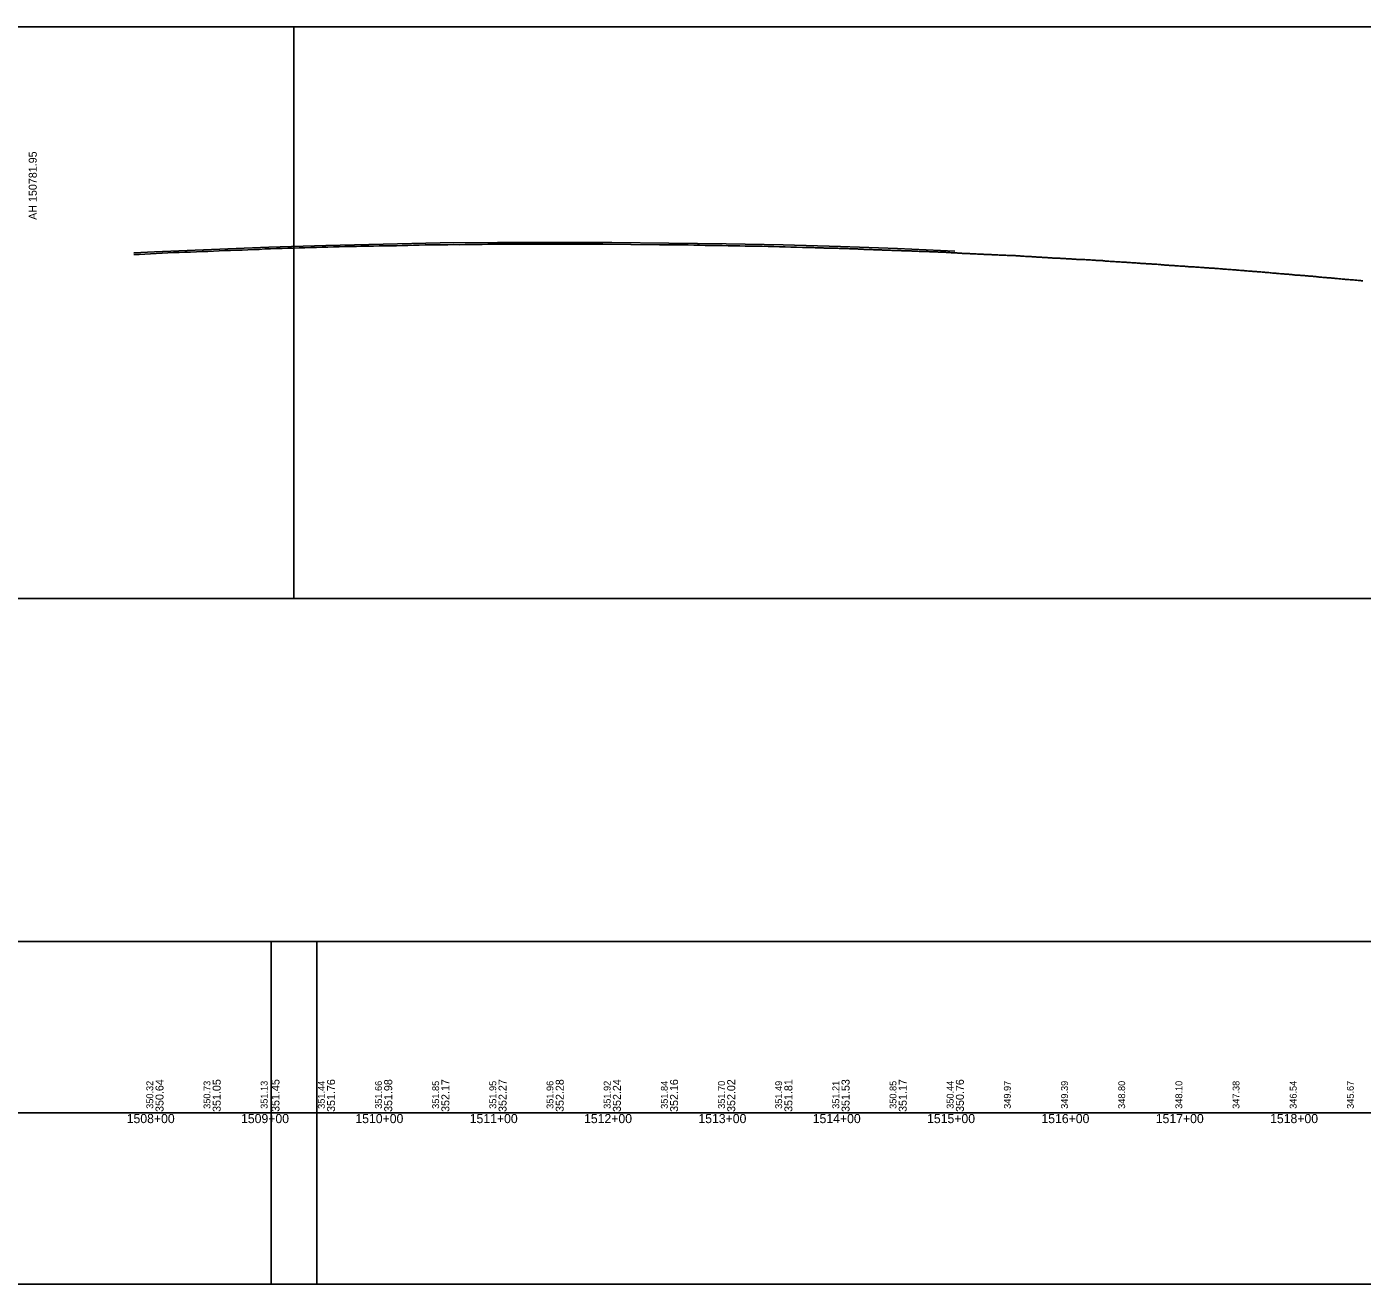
# Model space of a CAD drawing. Extents: x 2898 to 49495, y -15038 to -13538.
# Drawn here: x 40242 to 41410, y -15038 to -13938 of the extents above; entities that cross this region are included whole.
import ezdxf

# ---------------------------------------------------------------- set-up
doc = ezdxf.new("R2010")
doc.units = 0
for name, color, linetype in [('RD_DDB_Profile_EX', 7, 'Continuous'), ('RD_DDB_Profile_PR', 7, 'Continuous'), ('RD_DDB_StaTX', 7, 'Continuous'), ('RD_DDB_StripGrade', 7, 'Continuous'), ('RD_GPK_Profile_Cell', 7, 'Continuous'), ('RD_SHT_ShtClip', 7, 'Continuous')]:
    doc.layers.add(name, color=color, linetype=linetype)

msp = doc.modelspace()

# ---------------------------------------------------------------- linework, layer by layer
at = {"layer": 'RD_DDB_Profile_EX'}
for points in [[(40335.3, -14137.8), (40340.1, -14137.6), (40345.1, -14137.3), (40350.1, -14137.1), (40355.1, -14136.8), (40360.1, -14136.6), (40365.1, -14136.4), (40370.1, -14136.1), (40375.1, -14135.9), (40380.1, -14135.7), (40385.1, -14135.6), (40390.1, -14135.4), (40395.1, -14135.1), (40400.1, -14135), (40405.1, -14134.8), (40410.1, -14134.5), (40415.1, -14134.3), (40420.1, -14134.1), (40425.1, -14133.9), (40430.1, -14133.8), (40435.1, -14133.6), (40440.1, -14133.4), (40445.1, -14133.2), (40450.1, -14132.9), (40455.1, -14132.8), (40460.1, -14132.6), (40465.1, -14132.5), (40470.1, -14132.2), (40475.1, -14132.1), (40480.1, -14132), (40485.1, -14131.9), (40490.1, -14131.6), (40495.1, -14131.5), (40500.1, -14131.4), (40505.1, -14131.2), (40510.1, -14131), (40515.1, -14130.9), (40520.1, -14130.8), (40525.1, -14130.7), (40530.1, -14130.6), (40534, -14130.5), (40535.1, -14130.5), (40540.1, -14130.3), (40545.1, -14130.3), (40550.1, -14130.2), (40555.1, -14130.1), (40560.1, -14130.1), (40565.1, -14130), (40570.1, -14129.9), (40575.1, -14129.7), (40580.1, -14129.6), (40585.1, -14129.6), (40590.1, -14129.4), (40595.1, -14129.3), (40600.1, -14129.3), (40605.1, -14129.2), (40610.1, -14129.2), (40615.1, -14129.1), (40620.1, -14129.2), (40625.1, -14129.1), (40630.1, -14129), (40635.1, -14129), (40640.1, -14128.9), (40645.1, -14128.8), (40650.1, -14128.8), (40655.1, -14128.7), (40660.1, -14128.7), (40665.1, -14128.7), (40670.1, -14128.7), (40675.1, -14128.7), (40699.7, -14128.7), (40700.3, -14128.7), (40725.1, -14128.7), (40730.1, -14128.6), (40735.1, -14128.7), (40740.1, -14128.8), (40745, -14128.8), (40745.7, -14128.8), (40770, -14129), (40770.5, -14129), (40795.1, -14129.2), (40800.1, -14129.2), (40805.1, -14129.3), (40810.1, -14129.4), (40815.1, -14129.4), (40820.1, -14129.4), (40825.1, -14129.6), (40830.1, -14129.6), (40835.1, -14129.7), (40840.1, -14129.7), (40845.1, -14129.8), (40850.1, -14129.9), (40855.1, -14130), (40860.1, -14130.1), (40865.4, -14130.1), (40870.1, -14130.3), (40871.6, -14130.3), (40875.1, -14130.3), (40880.1, -14130.4), (40885.1, -14130.5), (40890.1, -14130.6)], [(40890.1, -14130.6), (40895.1, -14130.8), (40900.1, -14130.9), (40905.1, -14131.1), (40910.1, -14131.2), (40915.1, -14131.4), (40920.1, -14131.5), (40925.1, -14131.6), (40930.2, -14131.7), (40931.2, -14131.8), (40932.2, -14131.8), (40933.2, -14131.9), (40934.2, -14131.9), (40935.2, -14131.9), (40936.2, -14132), (40937.2, -14132), (40938.2, -14132), (40939.2, -14132.1), (40940.2, -14132.1), (40941.2, -14132.1), (40942.2, -14132.1), (40943.2, -14132.1), (40944.2, -14132.2), (40945.2, -14132.2), (40946.2, -14132.2), (40947.2, -14132.2), (40948.2, -14132.3), (40949.2, -14132.3), (40950.2, -14132.3), (40951.2, -14132.3), (40952.2, -14132.4), (40953.2, -14132.4), (40954.2, -14132.5), (40955.2, -14132.5), (40956.2, -14132.5), (40957.2, -14132.6), (40958.2, -14132.5), (40959.2, -14132.5), (40960.2, -14132.6), (40961.2, -14132.7), (40962.2, -14132.7), (40963.2, -14132.7), (40964.2, -14132.8), (40965.2, -14132.7), (40966.2, -14132.7), (40967.2, -14132.8), (40968.2, -14132.9), (40969.2, -14133), (40970.2, -14133), (40971.2, -14133.1), (40972.2, -14133.1), (40973.2, -14133.1), (40974.2, -14133.2), (40974.8, -14133.2), (40975.2, -14133.3), (40976.2, -14133.3), (40977.2, -14133.3), (40978.2, -14133.3), (40979.2, -14133.4), (40980.2, -14133.4), (40981.2, -14133.4), (40982.2, -14133.5), (40983.2, -14133.5), (40984.2, -14133.6), (40985.2, -14133.6), (40986.2, -14133.6), (40987.2, -14133.7), (40988.2, -14133.7), (40989.2, -14133.7), (40990.2, -14133.8), (40991.2, -14133.8), (40992.2, -14133.8), (40993.2, -14133.8), (40994.2, -14133.9), (40995.2, -14133.9), (40995.5, -14133.9), (40996.2, -14133.9), (40996.7, -14134), (40997.2, -14134), (40998.3, -14134.1), (40999.2, -14134.1), (41000.2, -14134.1), (41001.2, -14134.1), (41002.2, -14134.2), (41003.2, -14134.2), (41004.2, -14134.3), (41005.2, -14134.3), (41006.2, -14134.3), (41007.2, -14134.4), (41008.2, -14134.4), (41009.2, -14134.5), (41010.2, -14134.5), (41011.2, -14134.5), (41012.2, -14134.5), (41013.2, -14134.6), (41014.2, -14134.6), (41015.2, -14134.6), (41016.2, -14134.7), (41017.2, -14134.8), (41018.2, -14134.8), (41019.2, -14134.9)], [(41019.2, -14134.9), (41020.2, -14134.9), (41021.2, -14134.9), (41022.2, -14135), (41023.2, -14135), (41024.2, -14135), (41025.2, -14135.1), (41026.2, -14135.1), (41027.2, -14135.2), (41028.2, -14135.2), (41029.2, -14135.2), (41030.2, -14135.2), (41031.2, -14135.3), (41032.2, -14135.4), (41033.2, -14135.4), (41034.2, -14135.5), (41035.2, -14135.5), (41036.2, -14135.5), (41037.2, -14135.5), (41038.2, -14135.5), (41039.2, -14135.6), (41040.2, -14135.6), (41041.2, -14135.6), (41042.2, -14135.7), (41043.2, -14135.7), (41044.2, -14135.7), (41045.2, -14135.8), (41046.2, -14135.9), (41047.2, -14135.9), (41048.2, -14136), (41049.2, -14136.1), (41050.2, -14136.2), (41051.2, -14136.2), (41052.2, -14136.2), (41053.2, -14136.3), (41054.2, -14136.3), (41055.2, -14136.4), (41056.2, -14136.5), (41057.2, -14136.6), (41058.2, -14136.6), (41059.2, -14136.6), (41060.2, -14136.7), (41061.2, -14136.8), (41062.2, -14136.8), (41063.2, -14136.8), (41064.2, -14136.9), (41065.2, -14136.9), (41066.2, -14136.9), (41067.2, -14137), (41068.2, -14137), (41069.2, -14137), (41070.2, -14137.1), (41071.2, -14137.2), (41072.2, -14137.2), (41073.2, -14137.3), (41074.2, -14137.3), (41075.2, -14137.4), (41076.2, -14137.5), (41077.2, -14137.5), (41078.2, -14137.5), (41079.2, -14137.6), (41080.2, -14137.6), (41081.2, -14137.7), (41082.2, -14137.7), (41083.2, -14137.8), (41084.2, -14137.8), (41085.2, -14137.8), (41086.2, -14137.9), (41087.2, -14137.9), (41088.2, -14137.9), (41089.2, -14138.1), (41090.2, -14138.1), (41091.2, -14138.1), (41092.2, -14138.2), (41093.2, -14138.2), (41094.2, -14138.2), (41095.2, -14138.3), (41096.2, -14138.4), (41097.2, -14138.4), (41098.2, -14138.4), (41099.2, -14138.5), (41100.2, -14138.5), (41101.2, -14138.6), (41102.2, -14138.6), (41103.2, -14138.6), (41104.2, -14138.7), (41105.2, -14138.7), (41106.2, -14138.7), (41107.2, -14138.8), (41108.2, -14138.9), (41109.2, -14138.9), (41110.2, -14139), (41111.2, -14139.1), (41112.2, -14139.1), (41113.2, -14139.2), (41114.2, -14139.3), (41115.2, -14139.4), (41116.2, -14139.4), (41117.2, -14139.5), (41118.2, -14139.5), (41119.2, -14139.6)], [(41119.2, -14139.6), (41120.2, -14139.6), (41121.2, -14139.7), (41122.2, -14139.7), (41123.2, -14139.7), (41124.2, -14139.8), (41125.2, -14139.9), (41126.2, -14139.9), (41127.2, -14139.9), (41128.2, -14140), (41129.2, -14140.1), (41130.2, -14140.2), (41131.2, -14140.2), (41132.2, -14140.3), (41133.2, -14140.3), (41134.2, -14140.4), (41135.2, -14140.5), (41136.2, -14140.5), (41137.2, -14140.6), (41138.2, -14140.7), (41139.2, -14140.8), (41140.2, -14140.8), (41141.2, -14140.8), (41142.2, -14140.9), (41143.2, -14140.9), (41144.2, -14140.9), (41145.2, -14141), (41146.2, -14141.1), (41147.2, -14141.1), (41148.2, -14141.2), (41149.2, -14141.3), (41150.2, -14141.3), (41151.2, -14141.4), (41152.2, -14141.5), (41153.2, -14141.5), (41154.2, -14141.6), (41155.2, -14141.6), (41156.2, -14141.7), (41157.2, -14141.8), (41158.2, -14141.9), (41159.2, -14141.9), (41160.2, -14142), (41161.2, -14142), (41162.2, -14142.1), (41163.2, -14142.1), (41164.2, -14142.2), (41165.2, -14142.2), (41166.2, -14142.2), (41167.2, -14142.2), (41168.2, -14142.3), (41169.2, -14142.5), (41170.2, -14142.5), (41171.2, -14142.5), (41172.2, -14142.5), (41173.2, -14142.6), (41174.2, -14142.7), (41175.2, -14142.7), (41176.2, -14142.8), (41177.2, -14142.9), (41178.2, -14143), (41179.2, -14143.1), (41180.2, -14143.1), (41181.2, -14143.1), (41181.6, -14143.1), (41182.2, -14143.1), (41182.5, -14143.1), (41183.2, -14143.2), (41184.4, -14143.3), (41185.2, -14143.4), (41186.2, -14143.4), (41187.2, -14143.5), (41188.2, -14143.6), (41189.2, -14143.7), (41190.2, -14143.7), (41191.2, -14143.8), (41192.2, -14143.8), (41193.2, -14143.9), (41194.2, -14144), (41195.2, -14144), (41196.2, -14144.1), (41197.2, -14144.2), (41198.2, -14144.2), (41199.2, -14144.3), (41200.2, -14144.3), (41201.2, -14144.4), (41202.2, -14144.5), (41203.2, -14144.5), (41204.2, -14144.6), (41205.2, -14144.7), (41206.2, -14144.7), (41207.2, -14144.8), (41208.2, -14144.9), (41209.2, -14145), (41210.2, -14145), (41211.2, -14145.1), (41212.2, -14145.1), (41213.2, -14145.3), (41214.2, -14145.3), (41215.2, -14145.4), (41216.2, -14145.5), (41217.2, -14145.5)], [(41217.2, -14145.5), (41218.2, -14145.6), (41219.2, -14145.7), (41220.2, -14145.7), (41221.2, -14145.8), (41222.2, -14145.8), (41223.2, -14146), (41224.2, -14146), (41225.2, -14146), (41226.2, -14146.1), (41227.2, -14146.1), (41228.2, -14146.2), (41229.2, -14146.3), (41230.2, -14146.3), (41231.2, -14146.4), (41232.2, -14146.5), (41233.2, -14146.6), (41234.2, -14146.7), (41235.2, -14146.7), (41236.2, -14146.8), (41237.2, -14146.9), (41238.2, -14147), (41239.2, -14147), (41240.2, -14147.1), (41241.2, -14147.2), (41242.2, -14147.3), (41243.2, -14147.3), (41244.2, -14147.4), (41245.2, -14147.4), (41246.2, -14147.5), (41247.2, -14147.5), (41248.2, -14147.5), (41249.2, -14147.7), (41250.2, -14147.8), (41251.2, -14147.8), (41252.2, -14147.9), (41253.2, -14148), (41254.2, -14148), (41255.2, -14148.1), (41256.2, -14148.1), (41257.2, -14148.3), (41258.2, -14148.4), (41259.2, -14148.4), (41260.2, -14148.4), (41261.2, -14148.5), (41262.2, -14148.6), (41263.2, -14148.6), (41264.2, -14148.8), (41265.2, -14148.8), (41266.2, -14148.8), (41267.2, -14148.9), (41268.2, -14149), (41269.2, -14149.1), (41270.2, -14149.1), (41271.2, -14149.2), (41272.2, -14149.3), (41273.2, -14149.4), (41274.2, -14149.4), (41275.2, -14149.5), (41276.2, -14149.6), (41277.2, -14149.6), (41278.2, -14149.7), (41279.2, -14149.8), (41280.2, -14149.8), (41281.2, -14149.9), (41282.2, -14149.9), (41283.2, -14150), (41284.2, -14150.1), (41285.2, -14150.2), (41286.2, -14150.2), (41287.2, -14150.3), (41288.2, -14150.4), (41289.2, -14150.5), (41290.2, -14150.6), (41291.2, -14150.6), (41292.2, -14150.7), (41293.2, -14150.8), (41294.2, -14150.8), (41295.2, -14150.9), (41296.2, -14151), (41297.2, -14151.1), (41298.2, -14151.2), (41299.2, -14151.2), (41300.2, -14151.3), (41301.2, -14151.4), (41302.2, -14151.5), (41303.2, -14151.6), (41304.2, -14151.7), (41305.2, -14151.7), (41306.2, -14151.8), (41307.2, -14151.9), (41308.2, -14152), (41309.2, -14152), (41310.2, -14152.2), (41311.2, -14152.2), (41312.2, -14152.3), (41313.2, -14152.4), (41314.2, -14152.5), (41315.2, -14152.6), (41316.2, -14152.6), (41317.2, -14152.7)], [(41317.2, -14152.7), (41318.2, -14152.8), (41319.2, -14152.9), (41320.2, -14153), (41321.2, -14153), (41322.2, -14153.1), (41323.2, -14153.2), (41324.2, -14153.3), (41325.2, -14153.5), (41326.2, -14153.5), (41327.2, -14153.5), (41328.2, -14153.5), (41329.2, -14153.7), (41330.2, -14153.8), (41331.2, -14153.9), (41332.2, -14153.9), (41333.2, -14154), (41334.2, -14154.1), (41335.2, -14154.2), (41336.2, -14154.3), (41337.2, -14154.4), (41338.2, -14154.5), (41339.2, -14154.5), (41340.2, -14154.6), (41341.2, -14154.7), (41342.2, -14154.8), (41343.2, -14154.9), (41344.2, -14155), (41345.2, -14155), (41346.2, -14155.1), (41347.2, -14155.2), (41348.2, -14155.3), (41349.2, -14155.4), (41350.2, -14155.5), (41351.2, -14155.7), (41352.2, -14155.7), (41353.2, -14155.8), (41354.2, -14155.8), (41355.2, -14155.9), (41356.2, -14156), (41357.2, -14156.1), (41358.2, -14156.2), (41359.2, -14156.2), (41360.2, -14156.3), (41361.2, -14156.4), (41362.2, -14156.5), (41363.2, -14156.6), (41364.2, -14156.6), (41365.2, -14156.7), (41366.2, -14156.8), (41367.2, -14156.9), (41368.2, -14157), (41369.2, -14157.1), (41370.2, -14157.2), (41371.2, -14157.3), (41372.2, -14157.4), (41373.2, -14157.5), (41374.2, -14157.5), (41375.2, -14157.7), (41376.2, -14157.8), (41377.2, -14157.8), (41378.2, -14157.9), (41379.2, -14158), (41380.2, -14158.1), (41381.2, -14158.2), (41382.2, -14158.2), (41383.2, -14158.3), (41384.2, -14158.5), (41385.2, -14158.5), (41386.2, -14158.7), (41387.2, -14158.7), (41388.2, -14158.8), (41389.2, -14158.9), (41390.2, -14159), (41391.2, -14159.1), (41392.2, -14159.2), (41393.2, -14159.3), (41394.2, -14159.4), (41395.2, -14159.5), (41396.2, -14159.5), (41397.2, -14159.6), (41398.2, -14159.7), (41399.2, -14159.8), (41400.2, -14159.8), (41401.2, -14159.9), (41402.2, -14160), (41403.2, -14160.1), (41404.2, -14160.2), (41405.2, -14160.3), (41406.2, -14160.4), (41407.2, -14160.5), (41408.2, -14160.6), (41409.2, -14160.7), (41410.2, -14160.8)]]:
    msp.add_lwpolyline(points, dxfattribs=at)
at = {"layer": 'RD_DDB_Profile_PR'}
msp.add_lwpolyline([(40335.3, -14136.2), (40353.4, -14135.3), (40403.4, -14133.2), (40453.4, -14131.2), (40503.4, -14129.7), (40553.4, -14128.6), (40603.4, -14127.6), (40653.4, -14127.1), (40703.4, -14127.1), (40753.4, -14127.3), (40803.4, -14127.7), (40853.4, -14128.4), (40903.4, -14129.4), (40953.4, -14130.8), (41003.4, -14132.6), (41053.4, -14134.7)], dxfattribs=at)
at = {"layer": 'RD_GPK_Profile_Cell'}
msp.add_line((2976.1, -14888.5), (48721.1, -14888.5), dxfattribs=at)
at = {"layer": 'RD_SHT_ShtClip'}
for points in [[(38975.4, -13938.5), (38975.4, -14438.5), (40475.4, -14438.5), (40475.4, -14438.5), (40475.4, -13938.5), (40475.4, -13938.5)], [(40475.4, -13938.5), (40475.4, -14438.5), (41975.4, -14438.5), (41975.4, -14438.5), (41975.4, -13938.5), (41975.4, -13938.5)], [(38955.4, -14738.5), (40495.4, -14738.5), (40495.4, -15038.5), (38955.4, -15038.5)], [(40455.4, -14738.5), (41995.4, -14738.5), (41995.4, -15038.5), (40455.4, -15038.5)]]:
    msp.add_lwpolyline(points, close=True, dxfattribs=at)

# ---------------------------------------------------------------- texts
at = {"layer": 'RD_DDB_Profile_PR'}
msp.add_text('AH 150781.95', height=7, rotation=90, dxfattribs=at).set_placement((40250.5, -14107.4))
at = {"layer": 'RD_DDB_StaTX'}
for s, p in [('1508+00', (40329.2, -14897.5)), ('1509+00', (40429.2, -14897.5)), ('1510+00', (40529.2, -14897.5)), ('1511+00', (40629.2, -14897.5)), ('1512+00', (40729.2, -14897.5)), ('1513+00', (40829.2, -14897.5)), ('1514+00', (40929.2, -14897.5)), ('1515+00', (41029.2, -14897.5)), ('1516+00', (41129.2, -14897.5)), ('1517+00', (41229.2, -14897.5)), ('1518+00', (41329.2, -14897.5))]:
    msp.add_text(s, height=8, dxfattribs=at).set_placement(p)
at = {"layer": 'RD_DDB_StripGrade'}
for s, height, p in [('350.32', 6, (40352.4, -14885)), ('350.64', 7, (40361.4, -14887.7)), ('350.73', 6, (40402.4, -14885)), ('351.05', 7, (40411.4, -14887.7)), ('351.13', 6, (40452.4, -14885)), ('351.45', 7, (40462.8, -14887.7)), ('351.44', 6, (40502.4, -14885)), ('351.76', 7, (40511.4, -14887.7)), ('351.66', 6, (40552.4, -14885)), ('351.98', 7, (40561.4, -14887.7)), ('351.85', 6, (40602.4, -14885)), ('352.17', 7, (40611.4, -14887.7)), ('351.95', 6, (40652.4, -14885)), ('352.27', 7, (40661.4, -14887.7)), ('351.96', 6, (40702.4, -14885)), ('352.28', 7, (40711.4, -14887.7)), ('351.92', 6, (40752.4, -14885)), ('352.24', 7, (40761.4, -14887.7)), ('351.84', 6, (40802.4, -14885)), ('352.16', 7, (40811.4, -14887.7)), ('351.70', 6, (40852.4, -14885)), ('352.02', 7, (40861.4, -14887.7)), ('351.49', 6, (40902.4, -14885)), ('351.81', 7, (40911.4, -14887.7)), ('351.21', 6, (40952.4, -14885)), ('351.53', 7, (40961.4, -14887.7)), ('350.85', 6, (41002.4, -14885)), ('351.17', 7, (41011.4, -14887.7)), ('350.44', 6, (41052.4, -14885)), ('350.76', 7, (41061.4, -14887.7)), ('349.97', 6, (41102.4, -14885)), ('349.39', 6, (41152.4, -14885)), ('348.80', 6, (41202.4, -14885)), ('348.10', 6, (41252.4, -14885)), ('347.38', 6, (41302.4, -14885)), ('346.54', 6, (41352.4, -14885)), ('345.67', 6, (41402.4, -14885))]:
    msp.add_text(s, height=height, rotation=90, dxfattribs=at).set_placement(p)

doc.saveas('drawing.dxf')
